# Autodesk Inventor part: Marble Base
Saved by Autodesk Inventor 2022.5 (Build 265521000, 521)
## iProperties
Created: 2024-07
Part Number: Marble Base
Material: Generic
Document SubType Name: Modeling
Designer: AdminForWorker
Density: 1 g/cm^3
Appearance: Default
Title: Marble Base
Author: AdminForWorker
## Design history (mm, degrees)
feature "Marble Base"
body "Solid1"
